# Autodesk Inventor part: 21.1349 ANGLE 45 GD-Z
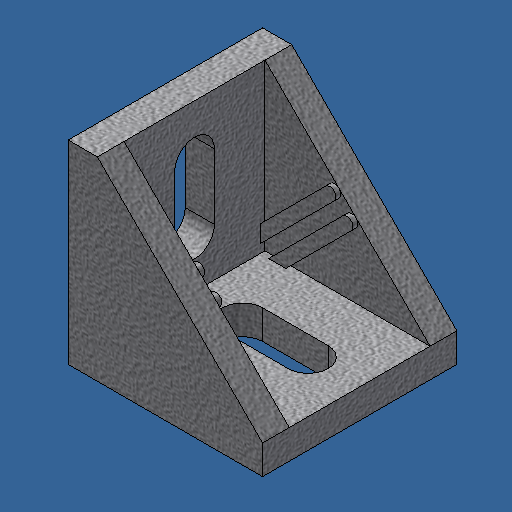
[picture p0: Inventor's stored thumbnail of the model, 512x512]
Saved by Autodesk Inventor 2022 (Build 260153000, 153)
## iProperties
Created: 2007-01
Part Number: 21.1349 ANGLE 45 GD-Z
Document SubType Name: Modeling
Designer: Andy Moles
Material: Aluminum-6061
Mass: 59.8075 g
Surface Area: 98.9545 cm^2
Volume: 22.1509 cm^3
Density: 2.7 g/cm^3
Appearance: Aluminum Cast
Author: Andy Moles
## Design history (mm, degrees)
sketch "Sketch1"
  geometry: L1 (0, 0)-(0, 40); L2 (0, 0)-(40, 0); L3 (40, 0)-(40, 6); L4 (0, 40)-(6, 40); L5 (40, 6)-(6, 40)
  constraints: 10 end point, 3 perpendicular, 1 vertical
  dimensions: "d0" = 40 distance of L1.start L1.end; "d1" = 40 distance of L1.start L2.end; "d2" = 6 distance of L1.end L4.end; "d3" = 6 distance of L2.end L3.end
extrude "Extrusion1" new body sketch "Sketch1" stored distance "d4" = 40; taper "d5" = 0 deg
workplane "Work Plane1"
sketch "Sketch2"
  geometry: L1 (-20, 34)-(-20, 0) reference; L2 (-20, 0)-(20, 0) reference; L3 (20, 0)-(20, 34) reference; L4 (-20, 34)-(20, 34) reference; L5 (-14.5, 34)-(14.5, 34); L6 (14.5, 34)-(14.5, 0); L7 (14.5, 0)-(-14.5, 0); L8 (-14.5, 0)-(-14.5, 34); 1 further point
  constraints: 8 end point, 2 parallel, 2 point on line, 1 horizontal, 1 perpendicular
  dimensions: "d7" = 5.5 distance between parallel lines of L8 L1; "d8" = 5.5 distance between parallel lines of L3 L6
extrude "Extrusion2" cut sketch "Sketch2" extent not by distance; stored distance "d9" = 40; taper "d10" = 0 deg
sketch "Sketch3"
  geometry: L1 (0, -14.5)-(0, 14.5) reference; L2 (-34, -20)-(0, -20) reference; L3 (-24.1, 4.1)-(-10.6, 4.1); L4 (-10.6, -4.1)-(-24.1, -4.1); A1 r 4.1 centre (-24.1, 0) between (-24.1, 4.1) and (-24.1, -4.1); A2 r 4.1 centre (-10.6, 0) between (-10.6, -4.1) and (-10.6, 4.1); 1 further point
  constraints: 4 end point, 4 point on circle, 3 tangent, 2 centre point, 1 horizontal alignment, 1 parallel
  dimensions: "d11" = 8.2 diameter of A1; "d12" = 8.2 diameter of A2; "d13" = 13.5 distance of A1.centre A2.centre; "d14" = 20 distance from line of A2.centre L2; "d15" = 6.5 distance edge to line of A2 L1
extrude "Extrusion3" cut sketch "Sketch3" extent not by distance; stored distance "d16" = 40; taper "d17" = 0 deg
sketch "Sketch4"
  geometry: L1 (0, 34)-(29, 34) reference; L2 (29, 0)-(29, 34) reference; L3 (18.6, 23.4)-(18.6, 9.9); L4 (10.4, 23.4)-(10.4, 9.9); L5 (34.5, 0)-(34.5, 34) reference; A1 r 4.1 centre (14.5, 9.9) between (10.4, 9.9) and (18.6, 9.9); A2 r 4.1 centre (14.5, 23.4) between (18.6, 23.4) and (10.4, 23.4); 1 further point
  constraints: 4 end point, 4 point on circle, 3 tangent, 2 centre point, 1 parallel, 1 vertical alignment
  dimensions: "d18" = 8.2 diameter of A1; "d19" = 8.2 diameter of A2; "d20" = 13.5 distance of A2.centre A1.centre; "d21" = 20 distance from line of A2.centre L5; "d22" = 6.5 distance edge to line of A2 L1
extrude "Extrusion4" cut sketch "Sketch4" extent not by distance; stored distance "d23" = 40; taper "d24" = 0 deg
workplane "Work Plane2"
sketch "Sketch5"
  geometry: L1 (40, 0)-(0, 0) reference; L2 (0, 0)-(4.5, 0); L3 (4.5, 0)-(0, 4.5); L4 (0, 4.5)-(0, 0); L5 (38.182, 0)-(35, 3.182); L6 (35, 3.182)-(31.818, 0); L7 (40, 6)-(40, 0) reference; L8 (0, 0)-(0, 40) reference; L9 (0, 38.182)-(3.182, 35); L10 (3.182, 35)-(0, 31.818); L11 (0, 40)-(6, 40) reference
  constraints: 14 end point, 5 perpendicular, 5 point on line, 1 parallel
  dimensions: "d25" = 4.5 distance of L1.end L2.end; "d26" = 4.5 distance of L5.start L5.end; "d27" = 5 distance from line of L5.end L7; "d28" = 4.5 distance of L9.end L10.end; "d29" = 5 distance from line of L9.end L11
extrude "Extrusion5" cut sketch "Sketch5" stored distance "d30" = 12.7; taper "d31" = 0 deg
sketch "Sketch6"
  geometry: L1 (4.5, 12.7)-(4.5, 0) reference; L2 (4.3, 2.25)-(3.1, 2.25); L3 (3.1, 2.25)-(3.1, 10.45); L4 (3.1, 10.45)-(4.3, 10.45); L5 (4.3, 10.45)-(4.3, 2.25); 3 further points
  constraints: 8 end point, 2 midpoint, 2 parallel, 1 horizontal, 1 horizontal alignment, 1 perpendicular
  dimensions: "d32" = 8.2 distance of L2.end L3.end; "d33" = 1.2 distance of L3.end L4.end; "d34" = 0.2 distance between parallel lines of L1 L5
extrude "Extrusion6" join sketch "Sketch6" distance "d35" = 4; taper "d36" = 0 deg
sketch "Sketch7"
  geometry: L1 (-5.817, 12.7)-(-5.817, 0); L2 (-6.017, 2.25)-(-7.217, 2.25); L3 (-7.217, 2.25)-(-7.217, 10.45); L4 (-7.217, 10.45)-(-6.017, 10.45); L5 (-6.017, 10.45)-(-6.017, 2.25); L6 (-5.817, 12.7)-(-5.817, 0) reference; 3 further points
  constraints: 10 end point, 2 midpoint, 2 parallel, 1 collinear, 1 horizontal, 1 horizontal alignment, 1 perpendicular
  dimensions: "d39" = 8.2 distance of L2.end L3.end; "d38" = 1.2 distance of L3.end L4.end; "d37" = 0.2 distance between parallel lines of L1 L5
extrude "Extrusion7" join sketch "Sketch7" taper "d41" = 0 deg; distance "d42" = 4
sketch "Sketch8"
  geometry: L1 (-5.168, 12.119)-(-5.168, 0); L2 (-5.368, 1.96)-(-6.568, 1.96); L3 (-6.568, 1.96)-(-6.568, 10.16); L4 (-6.568, 10.16)-(-5.368, 10.16); L5 (-5.368, 10.16)-(-5.368, 1.96); L6 (-5.168, 12.7)-(-5.168, 0); L7 (-10.132, 1.96)-(-11.332, 1.96) reference; L8 (-5.168, 12.41)-(-5.168, -0.29) reference; 3 further points
  constraints: 12 end point, 3 collinear, 2 midpoint, 2 parallel, 1 horizontal, 1 horizontal alignment, 1 perpendicular
  dimensions: "d45" = 8.2 distance of L2.end L3.end; "d44" = 1.2 distance of L3.end L4.end; "d43" = 0.2 distance between parallel lines of L1 L5
extrude "Extrusion8" join sketch "Sketch8" taper "d47" = 0 deg; distance "d48" = 4
sketch "Sketch9"
  geometry: L1 (-5.386, 12.454)-(-5.386, 0); L2 (-5.586, 2.127)-(-6.786, 2.127); L3 (-6.786, 2.127)-(-6.786, 10.327); L4 (-6.786, 10.327)-(-5.586, 10.327); L5 (-5.586, 10.327)-(-5.586, 2.127); L6 (-5.386, 12.7)-(-5.386, 0); L7 (-5.386, 12.577)-(-5.386, -0.123) reference; 3 further points
  constraints: 12 end point, 3 midpoint, 2 parallel, 1 collinear, 1 horizontal, 1 horizontal alignment, 1 perpendicular
  dimensions: "d51" = 8.2 distance of L2.end L3.end; "d50" = 1.2 distance of L3.end L4.end; "d49" = 0.2 distance between parallel lines of L1 L5
extrude "Extrusion9" join sketch "Sketch9" taper "d53" = 0 deg; distance "d54" = 4
sketch "Sketch10"
  geometry: L1 (34, 0)-(0, 0); L2 (0, 0)-(0, 34); L3 (0, 34)-(34, 0); L4 (0, 0)-(17, 17); L5 (0, 5.303)-(13.464, 18.768); L6 (0, 1.768)-(15.232, 17); L7 (0, 5.303)-(0, 1.768); L8 (5.303, 0)-(1.768, 0); L9 (5.303, 0)-(18.768, 13.464); L10 (1.768, 0)-(17, 15.232); A1 r 1.25 centre (14.348, 17.884) between (15.232, 17) and (13.464, 18.768); A2 r 1.25 centre (17.884, 14.348) between (18.768, 13.464) and (17, 15.232); 1 further point
  constraints: 20 end point, 5 symmetric about line, 4 point on circle, 2 centre point, 2 point on line, 2 tangent, 1 midpoint, 1 parallel, 1 perpendicular, 1 other
  dimensions: "d55" = 2.5 distance between parallel lines of L6 L5; "d56" = 1.25 distance between parallel lines of L4 L6; "d57" = 2.5 diameter of A1
extrude "Extrusion10" join sketch "Sketch10" distance "d58" = 1; taper "d59" = 0 deg
mirror "Mirror1"
body "Solid1"
node "Projected Loop1"
other parameters: "d6" = 90 deg
